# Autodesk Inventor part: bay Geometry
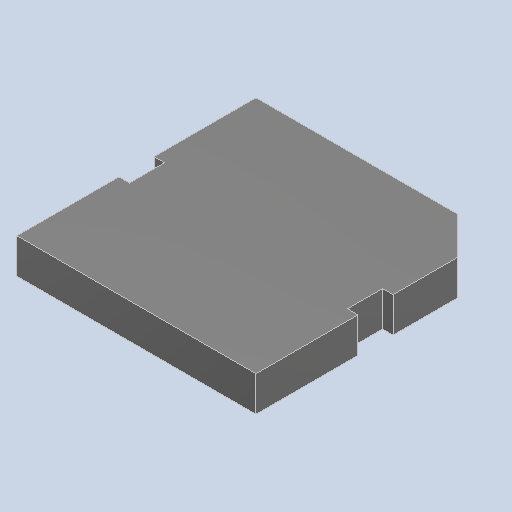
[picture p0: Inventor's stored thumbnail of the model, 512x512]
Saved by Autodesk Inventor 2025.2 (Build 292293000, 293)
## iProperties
Created: 2025-04
Part Number: bay Geometry
Material: Generic
Description: PART-bay Geometry-DESC
Document SubType Name: Modeling
Designer: BennF
Density: 1 g/cm^3
Appearance: Default
Author: BennF
Revision Number: NONE
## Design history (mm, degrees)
feature "bay"
body "Solid1"
